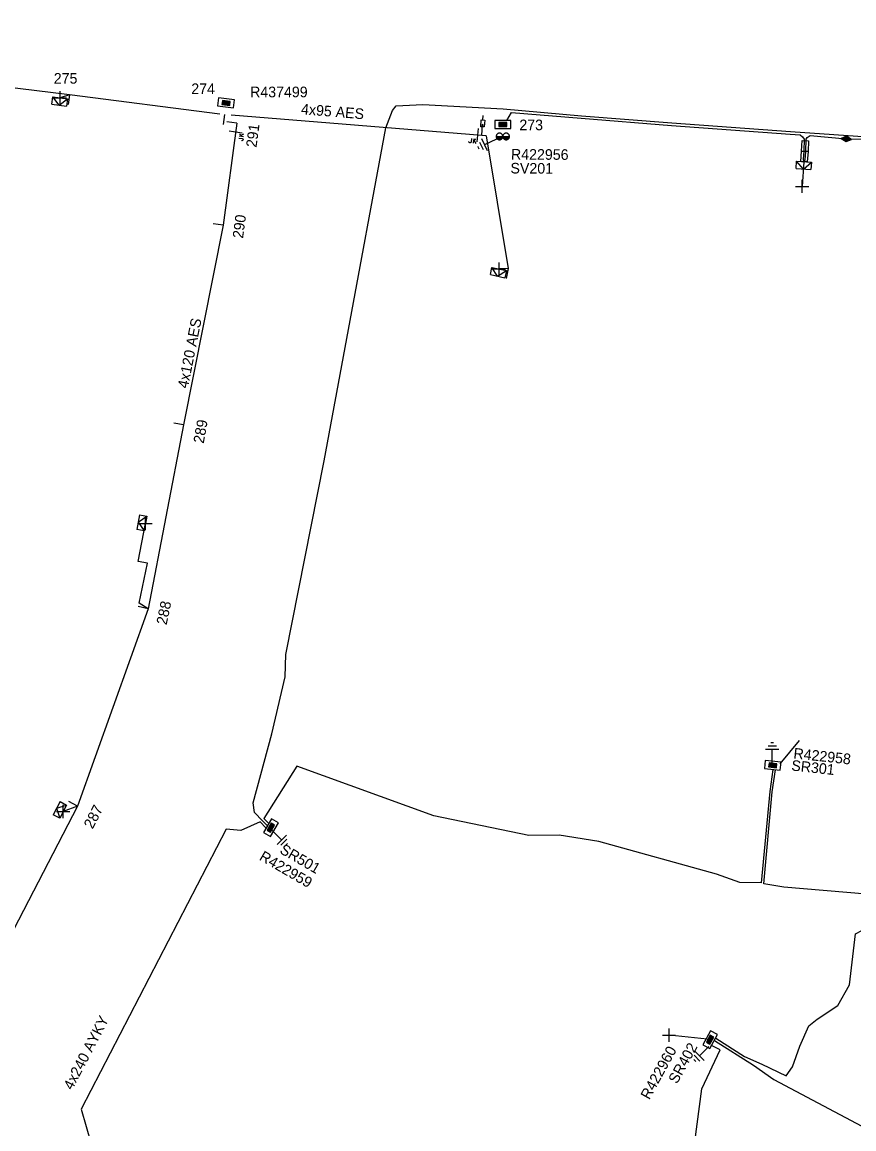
# Model space of a CAD drawing. Extents: x -540466 to -537383, y -1184038 to -1179972.
# Drawn here: x -537932.4 to -537854, y -1180719.7 to -1180615.3 of the extents above; entities that cross this region are included whole.
import ezdxf

# ---------------------------------------------------------------- set-up
doc = ezdxf.new("R2010")
doc.units = 0
for name, color, linetype in [('Vrstva 1', 7, 'Continuous'), ('Vrstva 13', 7, 'Continuous'), ('Vrstva 14', 7, 'Continuous'), ('Vrstva 15', 7, 'Continuous'), ('Vrstva 16', 7, 'Continuous'), ('Vrstva 18', 7, 'Continuous'), ('Vrstva 19', 7, 'Continuous'), ('Vrstva 2', 7, 'Continuous'), ('Vrstva 20', 7, 'Continuous'), ('Vrstva 28', 7, 'Continuous'), ('Vrstva 29', 7, 'Continuous'), ('Vrstva 30', 7, 'Continuous'), ('Vrstva 31', 7, 'Continuous'), ('Vrstva 34', 7, 'Continuous'), ('Vrstva 4', 7, 'Continuous'), ('Vrstva 5', 7, 'Continuous'), ('Vrstva 50', 7, 'Continuous'), ('Vrstva 51', 7, 'Continuous'), ('Vrstva 52', 7, 'Continuous'), ('Vrstva 54', 7, 'Continuous'), ('Vrstva 59', 7, 'Continuous'), ('Vrstva 6', 7, 'Continuous'), ('Vrstva 8', 7, 'Continuous'), ('Vrstva 9', 7, 'Continuous')]:
    doc.layers.add(name, color=color, linetype=linetype)

# ---------------------------------------------------------------- blocks, each defined once
blk = doc.blocks.new('NN450')
at = {"layer": 'Vrstva 2'}
for points in [[(0, 0), (0, 0.07), (-0.01, 0.13), (-0.03, 0.19), (-0.05, 0.25), (-0.08, 0.31), (-0.12, 0.37), (-0.16, 0.42), (-0.21, 0.46), (-0.26, 0.51), (-0.31, 0.54), (-0.37, 0.57), (-0.43, 0.59), (-0.5, 0.61), (-0.56, 0.62), (-0.63, 0.62), (-0.69, 0.62), (-0.75, 0.61), (-0.82, 0.59), (-0.88, 0.57), (-0.94, 0.54), (-0.99, 0.51), (-1.04, 0.46), (-1.09, 0.42), (-1.13, 0.37), (-1.17, 0.31), (-1.2, 0.25), (-1.22, 0.19), (-1.24, 0.13), (-1.25, 0.07), (-1.25, 0), (-1.25, -0.07), (-1.24, -0.13), (-1.22, -0.19), (-1.2, -0.25), (-1.17, -0.31), (-1.13, -0.37), (-1.09, -0.42), (-1.04, -0.46), (-0.99, -0.51), (-0.94, -0.54), (-0.88, -0.57), (-0.82, -0.59), (-0.75, -0.61), (-0.69, -0.62), (-0.62, -0.63), (-0.56, -0.62), (-0.5, -0.61), (-0.43, -0.59), (-0.37, -0.57), (-0.31, -0.54), (-0.26, -0.51), (-0.21, -0.46), (-0.16, -0.42), (-0.12, -0.37), (-0.08, -0.31), (-0.05, -0.25), (-0.03, -0.19), (-0.01, -0.13), (0, -0.07), (0, 0)], [(1.25, 0), (1.25, 0.07), (1.24, 0.13), (1.22, 0.19), (1.2, 0.25), (1.17, 0.31), (1.13, 0.37), (1.09, 0.42), (1.04, 0.46), (0.99, 0.51), (0.94, 0.54), (0.88, 0.57), (0.82, 0.59), (0.75, 0.61), (0.69, 0.62), (0.62, 0.62), (0.56, 0.62), (0.5, 0.61), (0.43, 0.59), (0.37, 0.57), (0.31, 0.54), (0.26, 0.51), (0.21, 0.46), (0.16, 0.42), (0.12, 0.37), (0.08, 0.31), (0.05, 0.25), (0.03, 0.19), (0.01, 0.13), (0, 0.07), (0, 0), (0, -0.07), (0.01, -0.13), (0.03, -0.19), (0.05, -0.25), (0.08, -0.31), (0.12, -0.37), (0.16, -0.42), (0.21, -0.46), (0.26, -0.51), (0.31, -0.54), (0.37, -0.57), (0.43, -0.59), (0.5, -0.61), (0.56, -0.62), (0.63, -0.63), (0.69, -0.62), (0.75, -0.61), (0.82, -0.59), (0.88, -0.57), (0.94, -0.54), (0.99, -0.51), (1.04, -0.46), (1.09, -0.42), (1.13, -0.37), (1.17, -0.31), (1.2, -0.25), (1.22, -0.19), (1.24, -0.13), (1.25, -0.07), (1.25, 0)], [(-1.25, 0), (1.25, 0)], [(-1.23, -0.16), (-0.02, -0.16)], [(-1.16, -0.32), (-0.09, -0.32)], [(-1.03, -0.47), (-0.22, -0.47)], [(0.02, -0.16), (1.23, -0.16)], [(0.09, -0.32), (1.16, -0.32)], [(0.22, -0.47), (1.03, -0.47)]]:
    blk.add_lwpolyline(points, dxfattribs=at)
blk = doc.blocks.new('NN840')
at = {"layer": 'Vrstva 15'}
for points in [[(0, 0.62), (0, -0.63)], [(-0.75, -0.71), (-0.75, -0.66)], [(-0.73, -0.76), (-0.75, -0.71)], [(-0.66, -0.8), (-0.73, -0.76)], [(-0.63, -0.8), (-0.66, -0.8)], [(-0.56, -0.76), (-0.63, -0.8)], [(-0.54, -0.71), (-0.56, -0.76)], [(-0.54, -0.38), (-0.54, -0.71)], [(-0.33, -0.38), (-0.33, -0.8)], [(-0.33, -0.64), (-0.13, -0.38)], [(-0.26, -0.56), (-0.09, -0.8)]]:
    blk.add_lwpolyline(points, dxfattribs=at)
blk = doc.blocks.new('NN870')
at = {"layer": 'Vrstva 4'}
for points in [[(0, -0.25), (0.5, 0), (0, 0.25), (-0.5, 0), (0, -0.25)], [(0.37, 0), (0, 0.19), (-0.36, 0), (0, -0.19), (0.37, 0)], [(0.24, 0), (0, 0.12), (-0.25, 0), (0, -0.12), (0.24, 0)], [(0.12, 0), (0, 0.06), (-0.13, 0), (0, -0.06), (0.12, 0)]]:
    blk.add_lwpolyline(points, dxfattribs=at)
blk = doc.blocks.new('NN800')
at = {"layer": 'Vrstva 1'}
for points in [[(-0.44, 0.44), (0.44, -0.44)], [(-0.44, -0.44), (0.44, 0.44)]]:
    blk.add_lwpolyline(points, dxfattribs=at)
blk = doc.blocks.new('NN820')
at = {"layer": 'Vrstva 13'}
for points in [[(0, 0), (0, -1.05)], [(-0.16, -0.81), (0.16, -0.81)], [(-0.16, -1.47), (-0.16, -0.81)], [(0, -1.05), (-0.06, -0.93)], [(0, -1.05), (0.06, -0.93)], [(0.16, -0.81), (0.16, -1.47)], [(0.16, -1.47), (-0.16, -1.47)], [(0, -1.47), (0, -1.87)]]:
    blk.add_lwpolyline(points, dxfattribs=at)
blk = doc.blocks.new('NN620')
at = {"layer": 'Vrstva 8'}
for points in [[(0.75, 0), (-0.75, 0)], [(-0.75, 0), (-0.75, -0.75)], [(0.75, -0.75), (0.75, 0)], [(-0.75, -0.75), (0.75, -0.75)], [(0.37, -0.18), (-0.38, -0.18)], [(-0.38, -0.18), (-0.38, -0.56)], [(-0.38, -0.56), (0.37, -0.56)], [(0.32, -0.23), (-0.33, -0.23)], [(-0.33, -0.23), (-0.33, -0.51)], [(-0.33, -0.51), (0.32, -0.51)], [(0.27, -0.27), (-0.28, -0.27)], [(-0.28, -0.27), (-0.28, -0.46)], [(-0.28, -0.46), (0.27, -0.46)], [(0.23, -0.32), (-0.23, -0.32)], [(-0.23, -0.32), (-0.23, -0.42)], [(-0.23, -0.42), (0.23, -0.42)], [(-0.19, -0.37), (0.19, -0.37)], [(0.23, -0.42), (0.23, -0.32)], [(0.27, -0.46), (0.27, -0.27)], [(0.32, -0.51), (0.32, -0.23)], [(0.37, -0.56), (0.37, -0.18)]]:
    blk.add_lwpolyline(points, dxfattribs=at)
blk = doc.blocks.new('NN630')
at = {"layer": 'Vrstva 9'}
for points in [[(0, -0.7), (-0.7, 0)], [(-0.7, -0.7), (-0.7, 0), (0.7, 0), (0.7, -0.7)], [(-0.7, -0.7), (0.7, -0.7)], [(0, -0.7), (0.7, 0)]]:
    blk.add_lwpolyline(points, dxfattribs=at)
blk = doc.blocks.new('NN810')
at = {"layer": 'Vrstva 14'}
for points in [[(0, -0.64), (0, -1.89)], [(0.63, -1.89), (-0.62, -1.89)], [(0.39, -2.2), (-0.4, -2.2)], [(0, -2.52), (-0.12, -2.52)], [(0.14, -2.52), (0, -2.52)]]:
    blk.add_lwpolyline(points, dxfattribs=at)
blk = doc.blocks.new('NN510')
at = {"layer": 'Vrstva 2'}
blk.add_lwpolyline([(0, 0), (0, 0.94)], dxfattribs=at)

msp = doc.modelspace()

# ---------------------------------------------------------------- linework, layer by layer
at = {"layer": 'Vrstva 20'}
for points in [[(-537858.26, -1180626.48), (-537858.3, -1180627.49), (-537858.9, -1180627.47), (-537858.86, -1180626.46)], [(-537858.98, -1180628.43), (-537858.9, -1180627.46), (-537858.3, -1180627.5), (-537858.38, -1180628.47)]]:
    msp.add_lwpolyline(points, close=True, dxfattribs=at)
at = {"layer": 'Vrstva 5'}
for points in [[(-537909.31, -1180691.06), (-537909.75, -1180690.63), (-537910.51, -1180689.86), (-537910.64, -1180688.94), (-537908.88, -1180682.44), (-537907.61, -1180677.05), (-537907.55, -1180674.95), (-537903.95, -1180656.66), (-537901.81, -1180645.14), (-537898.14, -1180625.27), (-537897.51, -1180623.62), (-537897.15, -1180623.19), (-537894.65, -1180623.04), (-537887.06, -1180623.47), (-537879.68, -1180624.11), (-537871.16, -1180624.78), (-537859.96, -1180625.61), (-537842.69, -1180626.79), (-537836.84, -1180627.63), (-537831.04, -1180627.98), (-537820.1, -1180628.88), (-537819.2, -1180630.08), (-537818.39, -1180630.39), (-537818.28, -1180631.48)], [(-537886.7, -1180624.58), (-537886.26, -1180623.81), (-537879.7, -1180624.35), (-537871.18, -1180625.04), (-537859.98, -1180625.86), (-537859.05, -1180625.91), (-537858.81, -1180626.12), (-537858.66, -1180626.33), (-537858.7, -1180627.47), (-537858.76, -1180628.24), (-537858.68, -1180628.45)], [(-537858.68, -1180628.45), (-537858.56, -1180628.26), (-537858.5, -1180627.49), (-537858.46, -1180626.31), (-537858.37, -1180626.17), (-537858.1, -1180625.97), (-537854.69, -1180626.3)], [(-537854.69, -1180626.3), (-537853.24, -1180626.32), (-537844.92, -1180626.88), (-537843.93, -1180627.05)], [(-537861.63, -1180685.8), (-537861.91, -1180687.88), (-537862.72, -1180696.48), (-537864.74, -1180696.44), (-537866.92, -1180695.66), (-537878.04, -1180692.58), (-537881.77, -1180691.97), (-537884.64, -1180692.02), (-537893.59, -1180690.16), (-537906.52, -1180685.46), (-537909.62, -1180690.41), (-537909.18, -1180690.84)], [(-537826.57, -1180700.29), (-537827.18, -1180700.3), (-537829.92, -1180700.24), (-537852.35, -1180697.59), (-537852.79, -1180697.56), (-537860.57, -1180696.88), (-537862.47, -1180696.57), (-537861.67, -1180687.9), (-537861.38, -1180685.83)], [(-537909.44, -1180691.29), (-537909.99, -1180690.74), (-537911.8, -1180691.54), (-537913.18, -1180691.42), (-537926.87, -1180717.83), (-537925.93, -1180721.09), (-537924.2, -1180722.94), (-537919.24, -1180725.87), (-537919.25, -1180726.62), (-537921.48, -1180731.4), (-537921.72, -1180732.27)], [(-537867.13, -1180711.36), (-537863.43, -1180713.67), (-537861.51, -1180715.02), (-537853.21, -1180719.43), (-537844.7, -1180723.79), (-537839.97, -1180726.3), (-537839.11, -1180727.67), (-537838.35, -1180728.47), (-537838, -1180728.71), (-537836.84, -1180728.11), (-537833.5, -1180729.11), (-537825.87, -1180732.84), (-537821.59, -1180735.03), (-537820.11, -1180735.94), (-537820.56, -1180736.96), (-537820.94, -1180737.9)], [(-537870.4, -1180763.87), (-537870.01, -1180762.94), (-537869.81, -1180762.63), (-537877.5, -1180758.48), (-537878.66, -1180757.56), (-537884.73, -1180753.35), (-537888.8, -1180751.14), (-537889.07, -1180750.34), (-537885.47, -1180744.32), (-537883.54, -1180741.56), (-537881.65, -1180739.76), (-537879.52, -1180736.45), (-537875.01, -1180732.88), (-537870.07, -1180724.55), (-537868.97, -1180720.91), (-537868.31, -1180715.92), (-537866.59, -1180712.23), (-537867.39, -1180711.83)]]:
    msp.add_lwpolyline(points, dxfattribs=at)
at = {"layer": 'Vrstva 50'}
for points in [[(-537913.77, -1180623.96), (-537927.98, -1180622.13), (-537937.49, -1180620.97), (-537964.79, -1180619.93), (-538007.53, -1180631.08), (-538047.93, -1180634.94), (-538069.97, -1180615.28)], [(-537912.19, -1180624.81), (-537913.48, -1180634.44), (-537917.21, -1180653.27), (-537920.56, -1180670.62), (-537927.21, -1180689.24), (-537936.97, -1180708.01), (-537938.74, -1180708.55)], [(-537888.66, -1180626.01), (-537889.08, -1180625.97), (-537912.73, -1180624.06)]]:
    msp.add_lwpolyline(points, dxfattribs=at)
at = {"layer": 'Vrstva 52'}
msp.add_lwpolyline([(-537867.01, -1180711.14), (-537864.28, -1180712.85), (-537862.67, -1180713.6), (-537860.35, -1180714.7), (-537859.77, -1180713.84), (-537859.08, -1180711.89), (-537858.21, -1180709.98), (-537857.45, -1180709.34), (-537855.5, -1180708.05), (-537854.39, -1180706.1), (-537853.81, -1180701.3), (-537853.21, -1180700.99), (-537853.16, -1180700.95)], dxfattribs=at)
at = {"layer": 'Vrstva 54'}
for points in [[(-537920.56, -1180670.62), (-537921.39, -1180670.09), (-537920.6, -1180666.34), (-537921.48, -1180666.16), (-537920.8, -1180662.59)], [(-537927.21, -1180689.24), (-537928.56, -1180689.76)]]:
    msp.add_lwpolyline(points, dxfattribs=at)
at = {"layer": 'Vrstva 59'}
for points in [[(-537858.68, -1180628.45), (-537858.86, -1180630.78)], [(-537860.93, -1180685.24), (-537859.09, -1180683.05)], [(-537867.82, -1180711.22), (-537871.41, -1180710.85)]]:
    msp.add_lwpolyline(points, dxfattribs=at)
at = {"layer": 'Vrstva 8'}
for points in [[(-537927.98, -1180622.13), (-537928.86, -1180622.42)], [(-537888.66, -1180626.01), (-537886.57, -1180638.54), (-537887.43, -1180638.57)]]:
    msp.add_lwpolyline(points, dxfattribs=at)

# ---------------------------------------------------------------- block references
at = {"layer": 'Vrstva 13'}
for p, rotation in [((-537927.98, -1180622.13), 172.75510566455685), ((-537913.35, -1180624.01), 172.75510566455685), ((-537912.18, -1180624.81), 82.40180553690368), ((-537913.48, -1180634.44), 82.40180553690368), ((-537886.57, -1180638.54), 167.82687492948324), ((-537917.21, -1180653.27), 79.96978614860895), ((-537920.56, -1180670.62), 78.16397224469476), ((-537927.21, -1180689.24), 62.55184721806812)]:
    msp.add_blockref('NN510', p, dxfattribs=dict(at, rotation=rotation))
at = {"layer": 'Vrstva 13', "xscale": 0.5, "yscale": 0.5}
msp.add_blockref('NN450', (-537887.09, -1180626.07), dxfattribs=at)
at = {"layer": 'Vrstva 15'}
for p, rotation in [((-537887.09, -1180626.07), -65.18650837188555), ((-537861.67, -1180685.77), 180), ((-537909.29, -1180691.08), 45), ((-537867.21, -1180711.46), -45)]:
    msp.add_blockref('NN810', p, dxfattribs=dict(at, rotation=rotation))
at = {"layer": 'Vrstva 16', "rotation": 175.3789777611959}
msp.add_blockref('NN820', (-537889.08, -1180625.97), dxfattribs=at)
at = {"layer": 'Vrstva 18'}
for p, rotation in [((-537912.3, -1180625.63), 82.34341949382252), ((-537889.48, -1180625.94), -4.621508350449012)]:
    msp.add_blockref('NN840', p, dxfattribs=dict(at, rotation=rotation))
at = {"layer": 'Vrstva 19', "rotation": 174.47245978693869}
msp.add_blockref('NN870', (-537854.69, -1180626.3), dxfattribs=at)
at = {"layer": 'Vrstva 28'}
for p, rotation in [((-537913.25, -1180623.27), 172.67699996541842), ((-537887.09, -1180625.32), 179.67300004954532), ((-537861.67, -1180685.77), 173.8718276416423), ((-537909.29, -1180691.08), 59.82424448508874), ((-537867.21, -1180711.46), -118.90829165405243)]:
    msp.add_blockref('NN620', p, dxfattribs=dict(at, rotation=rotation))
at = {"layer": 'Vrstva 31'}
for p, rotation in [((-537928.86, -1180622.42), -7.244894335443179), ((-537858.68, -1180628.45), -4.34675545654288), ((-537887.43, -1180638.57), -12.173125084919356), ((-537920.8, -1180662.59), -100.94692228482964), ((-537928.56, -1180689.76), -117.44815278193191)]:
    msp.add_blockref('NN630', p, dxfattribs=dict(at, rotation=rotation))
at = {"layer": 'Vrstva 34'}
for p, rotation in [((-537928.86, -1180622.42), 45.00000009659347), ((-537858.86, -1180630.78), 45), ((-537887.43, -1180638.57), 45), ((-537920.8, -1180662.59), 45), ((-537928.56, -1180689.76), 45), ((-537871.41, -1180710.85), 45)]:
    msp.add_blockref('NN800', p, dxfattribs=dict(at, rotation=rotation))

# ---------------------------------------------------------------- texts
at = {"layer": 'Vrstva 14'}
for s, p in [('275', (-537929.45, -1180621.09)), ('274', (-537916.48, -1180622.07)), ('273', (-537885.53, -1180625.48))]:
    msp.add_text(s, height=1, dxfattribs=at).set_placement(p)
for s, rotation, p in [('291', 82.402, (-537910.33, -1180627.15)), ('290', 82.402, (-537911.6, -1180635.73)), ('289', 79.97, (-537915.31, -1180655.08)), ('288', 78.164, (-537918.81, -1180672.2)), ('287', 62.552, (-537925.79, -1180691.46))]:
    msp.add_text(s, height=1, rotation=rotation, dxfattribs=at).set_placement(p)
at = {"layer": 'Vrstva 29'}
msp.add_text('R437499', height=1, dxfattribs=at).set_placement((-537910.93, -1180622.37))
for s, rotation, p in [('R422956', 359.673, (-537886.32, -1180628.25)), ('R422958', 353.872, (-537859.71, -1180684.74)), ('R422959', 329.824, (-537910.14, -1180694.27)), ('R422960', 61.092, (-537873.28, -1180717))]:
    msp.add_text(s, height=1, rotation=rotation, dxfattribs=at).set_placement(p)
at = {"layer": 'Vrstva 30'}
for s, rotation, p in [('SV201', 359.673, (-537886.37, -1180629.56)), ('SR301', 353.872, (-537859.91, -1180685.88)), ('SR501', 329.824, (-537908.22, -1180693.62)), ('SR402', 61.092, (-537870.66, -1180715.51))]:
    msp.add_text(s, height=1, rotation=rotation, dxfattribs=at).set_placement(p)
at = {"layer": 'Vrstva 51'}
for s, rotation, p in [('4x95 AES', 355.379, (-537906.15, -1180623.97)), ('4x120 AES', 78.78, (-537916.8, -1180649.89))]:
    msp.add_text(s, height=1, rotation=rotation, dxfattribs=at).set_placement(p)
at = {"layer": 'Vrstva 6'}
msp.add_text('4x240 AYKY', height=1, rotation=62.599, dxfattribs=at).set_placement((-537927.71, -1180716.09))

doc.saveas('drawing.dxf')
